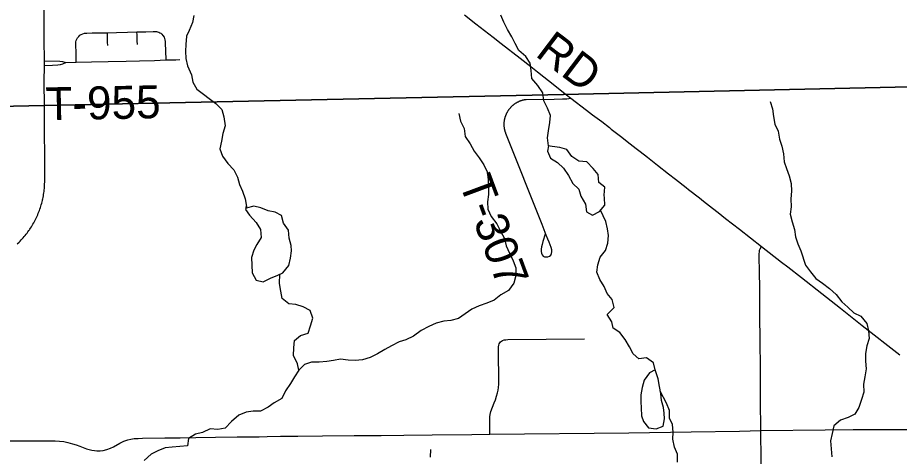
# Model space of a CAD drawing. Extents: x 0 to 34, y 0 to 22.
# Drawn here: x 5.217 to 5.977, y 17.563 to 17.941 of the extents above; entities that cross this region are included whole.
import ezdxf

# ---------------------------------------------------------------- set-up
doc = ezdxf.new("R2010")
doc.units = 0
for name, color, linetype in [('GM_X_County_Road', 7, 'Continuous'), ('GM_X_Minor_Lake', 7, 'Continuous'), ('GM_X_Minor_River', 7, 'Continuous'), ('GM_X_Township', 7, 'Continuous'), ('GM_X_Township_Road', 7, 'Continuous'), ('GM_X_Township_Road_Text', 7, 'Continuous'), ('GM_X_US_Route', 7, 'Continuous')]:
    doc.layers.add(name, color=color, linetype=linetype)

msp = doc.modelspace()

# ---------------------------------------------------------------- linework, layer by layer
at = {"layer": 'GM_X_County_Road'}
msp.add_lwpolyline([(5.20847, 17.576), (5.22729, 17.57592), (5.2446, 17.57599), (5.24938, 17.57584), (5.25317, 17.57558), (5.25684, 17.57531), (5.26026, 17.57464), (5.26428, 17.5734), (5.26745, 17.57247), (5.27072, 17.5713), (5.27635, 17.56911), (5.28089, 17.56785), (5.28316, 17.56752), (5.28535, 17.56735), (5.28803, 17.56726), (5.2908, 17.5676), (5.29383, 17.56836), (5.29702, 17.56962), (5.29962, 17.57089), (5.30509, 17.57399), (5.30854, 17.57567), (5.31215, 17.57693), (5.31465, 17.57744), (5.31761, 17.57785), (5.32105, 17.5781), (5.32475, 17.57819), (5.34394, 17.5784), (5.35406, 17.57854), (5.35715, 17.57859), (5.37072, 17.57877), (5.38758, 17.57901), (5.40628, 17.57927), (5.40937, 17.57931), (5.42518, 17.57953), (5.43204, 17.5797), (5.44364, 17.57987), (5.45345, 17.57992), (5.45857, 17.58), (5.47981, 17.58029), (5.50715, 17.58046), (5.53059, 17.58062), (5.54992, 17.58079), (5.57437, 17.58113), (5.60882, 17.58138), (5.62419, 17.58163), (5.74417, 17.58272), (5.79777, 17.58365), (5.83962, 17.5844), (5.8578, 17.58483), (5.91351, 17.58548), (5.93758, 17.5857), (5.96129, 17.58577), (5.99322, 17.58584)], dxfattribs=at)
at = {"layer": 'GM_X_Minor_Lake'}
for points in [[(5.67477, 17.83028), (5.67405, 17.82565), (5.67651, 17.81958), (5.68257, 17.81598), (5.68786, 17.81086), (5.69203, 17.8046), (5.69581, 17.79778), (5.70111, 17.79285), (5.70263, 17.78678), (5.70679, 17.77995), (5.70755, 17.77331), (5.71285, 17.77047), (5.7189, 17.7737), (5.72325, 17.77901), (5.72306, 17.78546)], [(5.67475, 17.83016), (5.67405, 17.82565), (5.67651, 17.81958), (5.68257, 17.81598), (5.68786, 17.81086), (5.69203, 17.8046), (5.69581, 17.79778), (5.70111, 17.79285), (5.70263, 17.78678), (5.70679, 17.77995), (5.70755, 17.77331), (5.71285, 17.77047), (5.7189, 17.7737), (5.72325, 17.77901), (5.72306, 17.78546)], [(5.72306, 17.78546), (5.72268, 17.78755), (5.72343, 17.79457), (5.71813, 17.79855), (5.71756, 17.80538), (5.71321, 17.81069), (5.70791, 17.81637), (5.7011, 17.81694), (5.69486, 17.82092), (5.69069, 17.82699), (5.68445, 17.82869), (5.67783, 17.82964), (5.67457, 17.83032)], [(5.72306, 17.78546), (5.72268, 17.78755), (5.72343, 17.79457), (5.71813, 17.79855), (5.71756, 17.80538), (5.71321, 17.81069), (5.70791, 17.81637), (5.7011, 17.81694), (5.69486, 17.82092), (5.69069, 17.82699), (5.68445, 17.82869), (5.67783, 17.82964), (5.67477, 17.83028)], [(5.41423, 17.77784), (5.41342, 17.77543), (5.41682, 17.7705), (5.42269, 17.76405), (5.42629, 17.75798), (5.42686, 17.75134), (5.42327, 17.74527), (5.42062, 17.74015), (5.41854, 17.73389), (5.41892, 17.72744), (5.4193, 17.72061), (5.42271, 17.71435), (5.42876, 17.71302), (5.43519, 17.71606), (5.44125, 17.71872)], [(5.41411, 17.77748), (5.41342, 17.77543), (5.41682, 17.7705), (5.42269, 17.76405), (5.42629, 17.75798), (5.42686, 17.75134), (5.42327, 17.74527), (5.42062, 17.74015), (5.41854, 17.73389), (5.41892, 17.72744), (5.4193, 17.72061), (5.42271, 17.71435), (5.42876, 17.71302), (5.43519, 17.71606), (5.44125, 17.71872)], [(5.44125, 17.71872), (5.4456, 17.72081), (5.45089, 17.72707), (5.45221, 17.73334), (5.45315, 17.73959), (5.45296, 17.74434), (5.45107, 17.7506), (5.4505, 17.75762), (5.44615, 17.76368), (5.44444, 17.77013), (5.43895, 17.77316), (5.43309, 17.7743), (5.42685, 17.77676), (5.4206, 17.77809), (5.41417, 17.77657), (5.41407, 17.77798)], [(5.44125, 17.71872), (5.4456, 17.72081), (5.45089, 17.72707), (5.45221, 17.73334), (5.45315, 17.73959), (5.45296, 17.74434), (5.45107, 17.7506), (5.4505, 17.75762), (5.44615, 17.76368), (5.44444, 17.77013), (5.43895, 17.77316), (5.43309, 17.7743), (5.42685, 17.77676), (5.4206, 17.77809), (5.41417, 17.77657), (5.41411, 17.77748)], [(5.76692, 17.63711), (5.76189, 17.63448), (5.75735, 17.62822), (5.75565, 17.62196), (5.75452, 17.61551), (5.75453, 17.60944), (5.75472, 17.60451), (5.7551, 17.59749), (5.7568, 17.59256), (5.76115, 17.58706)], [(5.76691, 17.63711), (5.76189, 17.63448), (5.75735, 17.62822), (5.75565, 17.62196), (5.75452, 17.61551), (5.75453, 17.60944), (5.75472, 17.60451), (5.7551, 17.59749), (5.7568, 17.59256), (5.76115, 17.58706)], [(5.76115, 17.58706), (5.76759, 17.5863), (5.77364, 17.58858), (5.77477, 17.59503), (5.77458, 17.59977), (5.77401, 17.60471), (5.77212, 17.61077), (5.77155, 17.61685), (5.7706, 17.62291), (5.76946, 17.62936), (5.76692, 17.63711)], [(5.76115, 17.58706), (5.76759, 17.5863), (5.77364, 17.58858), (5.77477, 17.59503), (5.77458, 17.59977), (5.77401, 17.60471), (5.77212, 17.61077), (5.77155, 17.61685), (5.7706, 17.62291), (5.76946, 17.62936), (5.76694, 17.63704)]]:
    msp.add_lwpolyline(points, dxfattribs=at)
at = {"layer": 'GM_X_Minor_River'}
for points in [[(5.36902, 17.94261), (5.36765, 17.93651), (5.36478, 17.92961), (5.36263, 17.92463), (5.36203, 17.91759)], [(5.67475, 17.83016), (5.67402, 17.83698), (5.67482, 17.84325), (5.67599, 17.8503), (5.67641, 17.85638), (5.674, 17.86259), (5.67083, 17.86897), (5.66991, 17.87596), (5.66561, 17.88212), (5.66036, 17.88826), (5.65983, 17.89508), (5.65912, 17.90133), (5.65539, 17.90731), (5.64922, 17.91229), (5.64606, 17.91829), (5.64327, 17.9243), (5.63935, 17.93047), (5.63636, 17.93685), (5.63377, 17.94286)], [(5.36203, 17.91759), (5.36179, 17.91171), (5.36212, 17.90545), (5.3634, 17.89903), (5.36679, 17.89152), (5.36807, 17.8851), (5.37143, 17.87892), (5.37739, 17.87488), (5.3822, 17.87101), (5.38779, 17.86658), (5.3932, 17.86159), (5.39486, 17.85517), (5.39598, 17.84742), (5.39386, 17.84092), (5.39288, 17.83426), (5.39133, 17.82758), (5.39356, 17.82118), (5.39824, 17.81503), (5.40348, 17.80946), (5.40646, 17.80308), (5.4083, 17.79686), (5.4109, 17.79104), (5.41313, 17.78445), (5.41423, 17.77784)], [(5.866, 17.86855), (5.86804, 17.86215), (5.86876, 17.85552), (5.87004, 17.84891), (5.87283, 17.84291), (5.87393, 17.8361), (5.87615, 17.82989), (5.87744, 17.82328), (5.87817, 17.81647), (5.88, 17.81063), (5.88223, 17.80423), (5.88408, 17.79782), (5.88424, 17.791), (5.88382, 17.78454), (5.88397, 17.77771), (5.88318, 17.77124), (5.88503, 17.76464), (5.88707, 17.75824), (5.88778, 17.75181), (5.88981, 17.74578), (5.89241, 17.73977), (5.89648, 17.72734), (5.90077, 17.72156), (5.90525, 17.71578), (5.91121, 17.71194), (5.91718, 17.70714), (5.92297, 17.70197), (5.92765, 17.69562), (5.93286, 17.69119), (5.93827, 17.68638), (5.9442, 17.6833), (5.94926, 17.67715), (5.95092, 17.67074), (5.95126, 17.66411), (5.94933, 17.6578), (5.94834, 17.65133), (5.94831, 17.6445), (5.94884, 17.63806), (5.94767, 17.6312), (5.9465, 17.62473), (5.94665, 17.6179), (5.94472, 17.61159), (5.94242, 17.60471), (5.93896, 17.59894), (5.93316, 17.59596), (5.92659, 17.59391), (5.92103, 17.58885), (5.91948, 17.58236), (5.91812, 17.57588), (5.91919, 17.56225)], [(5.59752, 17.85797), (5.59899, 17.85155), (5.60197, 17.84517), (5.60308, 17.83837), (5.60739, 17.83183), (5.61056, 17.82564), (5.61504, 17.81986), (5.61915, 17.81389), (5.62193, 17.80788), (5.62284, 17.80126), (5.62317, 17.7952), (5.62295, 17.78836), (5.62234, 17.7819), (5.62249, 17.77564), (5.62528, 17.76944), (5.63034, 17.76292), (5.63332, 17.75673), (5.63687, 17.75036), (5.63834, 17.74394), (5.64114, 17.73756), (5.64431, 17.73118), (5.64672, 17.72517), (5.64669, 17.71834), (5.64494, 17.71185), (5.64017, 17.70566), (5.63383, 17.70191), (5.62788, 17.69722), (5.62151, 17.69461), (5.61495, 17.69218), (5.60877, 17.68957), (5.603, 17.68545), (5.59724, 17.68133), (5.59065, 17.67966), (5.58462, 17.67896), (5.57803, 17.67747), (5.57149, 17.67448), (5.56495, 17.67091), (5.55844, 17.66621), (5.5517, 17.66302), (5.54607, 17.66137), (5.53953, 17.6578), (5.53355, 17.65463), (5.5274, 17.65088), (5.52104, 17.6477), (5.51447, 17.64584), (5.50805, 17.64531), (5.502, 17.64536), (5.49555, 17.64635), (5.48952, 17.64526), (5.48368, 17.64437), (5.47689, 17.64364), (5.47046, 17.64368), (5.46445, 17.64164), (5.45945, 17.63698), (5.45581, 17.63101), (5.45216, 17.62523), (5.44795, 17.61907), (5.44489, 17.61235), (5.43817, 17.60878), (5.43296, 17.60487), (5.42642, 17.60149), (5.41999, 17.60153), (5.41415, 17.60064), (5.40778, 17.59803), (5.40147, 17.59257), (5.39594, 17.58675), (5.38953, 17.58565), (5.38309, 17.58626), (5.37635, 17.58326), (5.37033, 17.58179), (5.36437, 17.57786), (5.36357, 17.57158), (5.35036, 17.57052), (5.34432, 17.57), (5.33795, 17.56738), (5.33215, 17.5644), (5.32603, 17.55914)], [(5.76694, 17.63708), (5.76548, 17.64311), (5.75932, 17.64752), (5.75272, 17.64661), (5.7479, 17.65086), (5.74454, 17.65705), (5.74099, 17.66323), (5.73632, 17.66919), (5.73056, 17.67304), (5.72949, 17.67852), (5.72537, 17.68487), (5.73147, 17.69089), (5.7298, 17.69768), (5.72533, 17.70289), (5.72292, 17.7091), (5.71919, 17.71489), (5.7164, 17.72128), (5.71739, 17.72775), (5.71931, 17.73425), (5.7241, 17.74005), (5.72603, 17.74635), (5.72645, 17.75282), (5.72575, 17.75868), (5.72428, 17.76491), (5.7197, 17.77481)], [(5.45945, 17.63698), (5.4582, 17.64226), (5.45481, 17.64958), (5.45504, 17.65623), (5.45565, 17.6625), (5.46104, 17.66661), (5.46742, 17.66865), (5.46954, 17.67515), (5.47147, 17.68165), (5.46924, 17.68843), (5.46311, 17.69151), (5.45683, 17.69345), (5.45076, 17.69407), (5.44518, 17.69849), (5.44389, 17.70491), (5.4428, 17.71153), (5.44308, 17.71948)], [(5.78616, 17.55765), (5.78601, 17.56448), (5.78341, 17.57049), (5.78212, 17.57748), (5.78235, 17.58355), (5.78183, 17.58999), (5.77924, 17.59562), (5.77909, 17.60207), (5.77648, 17.60846), (5.77114, 17.61872)], [(5.57313, 17.56183), (5.57336, 17.56847)]]:
    msp.add_lwpolyline(points, dxfattribs=at)
at = {"layer": 'GM_X_Township'}
for points in [[(6.70537, 19.6821), (6.70963, 19.16766), (6.71042, 19.04387), (6.71169, 18.92788), (6.71262, 18.76776), (6.71518, 18.37415), (6.71961, 17.89693), (6.52686, 17.89276), (6.52166, 17.89265), (6.51777, 17.89256), (6.14296, 17.88445), (5.68786, 17.8746), (5.23962, 17.86489), (4.75674, 17.85444)], [(4.29417, 16.81303), (4.29258, 17.16739), (4.29139, 17.31008), (4.28969, 17.51278), (4.28798, 17.71737), (4.28678, 17.83811), (4.28685, 17.84011), (4.28692, 17.84212), (4.28987, 17.8422), (4.75674, 17.85444), (5.23962, 17.86489), (5.68786, 17.8746), (6.14296, 17.88445), (6.51777, 17.89256), (6.52166, 17.89265), (6.52686, 17.89276), (6.71961, 17.89693), (6.72194, 17.73847), (6.72576, 17.34372), (6.73112, 16.77245)]]:
    msp.add_lwpolyline(points, dxfattribs=at)
at = {"layer": 'GM_X_Township_Road'}
msp.add_line((5.68625, 17.87747), (5.69023, 17.87429), dxfattribs=at)
for points in [[(5.60249, 17.94312), (5.61222, 17.93546), (5.627, 17.92399), (5.63397, 17.91851), (5.65037, 17.90585), (5.65961, 17.89859), (5.66544, 17.894), (5.68027, 17.88224), (5.68625, 17.87747)], [(5.26757, 17.90238), (5.26731, 17.91058), (5.26711, 17.91692), (5.26723, 17.91976), (5.26751, 17.92103), (5.26799, 17.92215), (5.26867, 17.92339), (5.26967, 17.92454), (5.2707, 17.9255), (5.2719, 17.92626), (5.27329, 17.92686), (5.27469, 17.92725), (5.27661, 17.92746), (5.28132, 17.92757), (5.29436, 17.92774), (5.3023, 17.92792), (5.3116, 17.92814), (5.3199, 17.92834), (5.3274, 17.92861), (5.33378, 17.92877), (5.33661, 17.92869), (5.33769, 17.92841), (5.33869, 17.92809), (5.33949, 17.9277), (5.3404, 17.92718), (5.34132, 17.92634), (5.34224, 17.92534), (5.34324, 17.92374), (5.34367, 17.92267), (5.34403, 17.92155), (5.34423, 17.9202), (5.34427, 17.91871), (5.34448, 17.91206), (5.34472, 17.90421)], [(5.29469, 17.91669), (5.2946, 17.91967), (5.29446, 17.92441), (5.29436, 17.92774)], [(5.32022, 17.91749), (5.32012, 17.92084), (5.31999, 17.92547), (5.3199, 17.92834)], [(5.24, 17.90343), (5.25328, 17.9033), (5.25575, 17.90288), (5.2586, 17.90205)], [(5.24001, 17.89931), (5.24699, 17.89986), (5.25152, 17.9), (5.2539, 17.9002), (5.25605, 17.90083), (5.2586, 17.90205)], [(5.2586, 17.90205), (5.26757, 17.90238), (5.28062, 17.90266), (5.29519, 17.90299), (5.31053, 17.90331), (5.32207, 17.90355), (5.33502, 17.90388), (5.34472, 17.90421), (5.34857, 17.90432), (5.35343, 17.90445), (5.35694, 17.90455)], [(5.67204, 17.75402), (5.67003, 17.74786), (5.66932, 17.74527), (5.66878, 17.74312), (5.66842, 17.7412), (5.66847, 17.73919), (5.66869, 17.73763), (5.66941, 17.73629), (5.6703, 17.73526), (5.67142, 17.73463), (5.67284, 17.73445), (5.67432, 17.73459), (5.67554, 17.73511), (5.67673, 17.73602), (5.6774, 17.73736), (5.67772, 17.73883), (5.67763, 17.74053), (5.677, 17.74259), (5.67633, 17.74477), (5.67544, 17.7471), (5.67432, 17.74987), (5.67291, 17.7532), (5.66923, 17.76238), (5.63806, 17.84087), (5.63789, 17.84134), (5.63776, 17.8417), (5.63764, 17.84205), (5.63753, 17.84242), (5.63742, 17.84278), (5.63732, 17.84314), (5.63722, 17.84351), (5.63713, 17.84388), (5.63705, 17.84425), (5.63698, 17.84462), (5.63691, 17.84499), (5.63685, 17.84537), (5.63679, 17.84574), (5.63674, 17.84612), (5.6367, 17.8465), (5.63667, 17.84687), (5.63671, 17.85104), (5.63675, 17.85141), (5.6368, 17.85179), (5.63685, 17.85217), (5.63692, 17.85254), (5.63699, 17.85291), (5.63706, 17.85328), (5.63714, 17.85365), (5.63723, 17.85402), (5.63733, 17.85439), (5.63743, 17.85475), (5.63754, 17.85512), (5.63765, 17.85548), (5.63777, 17.85584), (5.6379, 17.8562), (5.63803, 17.85655), (5.63817, 17.8569), (5.63832, 17.85725), (5.63847, 17.8576), (5.63863, 17.85794), (5.63879, 17.85829), (5.63896, 17.85863), (5.63914, 17.85896), (5.63932, 17.8593), (5.6395, 17.85963), (5.6397, 17.85995), (5.63989, 17.86027), (5.6401, 17.86059), (5.64031, 17.86091), (5.64052, 17.86122), (5.64074, 17.86153), (5.64097, 17.86184), (5.6412, 17.86214), (5.64144, 17.86243), (5.64168, 17.86273), (5.64193, 17.86301), (5.64218, 17.8633), (5.64243, 17.86358), (5.64269, 17.86385), (5.64296, 17.86412), (5.64323, 17.86439), (5.64351, 17.86465), (5.64379, 17.8649), (5.64407, 17.86516), (5.64436, 17.8654), (5.64465, 17.86564), (5.64495, 17.86588), (5.64525, 17.86611), (5.64555, 17.86633), (5.64586, 17.86655), (5.64618, 17.86677), (5.64649, 17.86698), (5.64681, 17.86718), (5.64714, 17.86738), (5.64746, 17.86757), (5.64779, 17.86776), (5.64813, 17.86794), (5.64846, 17.86811), (5.6488, 17.86828), (5.64914, 17.86844), (5.64949, 17.8686), (5.64984, 17.86875), (5.65019, 17.8689), (5.65054, 17.86903), (5.65089, 17.86917), (5.65125, 17.86929), (5.65161, 17.86941), (5.65197, 17.86953), (5.65234, 17.86963), (5.6527, 17.86973), (5.65307, 17.86983), (5.65344, 17.86992), (5.65381, 17.87), (5.65418, 17.87007), (5.65455, 17.87014), (5.65493, 17.8702), (5.6553, 17.87026), (5.65566, 17.87018), (5.67982, 17.87038), (5.68684, 17.8706), (5.69074, 17.87082), (5.6941, 17.87132)], [(5.69023, 17.87429), (5.6941, 17.87132), (5.70745, 17.86099), (5.71273, 17.85693), (5.72079, 17.85108), (5.72738, 17.84593), (5.72767, 17.8457), (5.72892, 17.84472), (5.73693, 17.83846), (5.74513, 17.83206), (5.74629, 17.83115), (5.74666, 17.83086), (5.75757, 17.82234), (5.76013, 17.82034), (5.76881, 17.81356), (5.77836, 17.8061), (5.78433, 17.80144), (5.79356, 17.79423), (5.79561, 17.79263), (5.80492, 17.78536), (5.80845, 17.7826), (5.81626, 17.7765), (5.82108, 17.77273), (5.82752, 17.7677), (5.8335, 17.76303), (5.83948, 17.75835), (5.85853, 17.74358), (5.87586, 17.73005), (5.88124, 17.72589), (5.89301, 17.71678), (5.90114, 17.71051), (5.90258, 17.70937), (5.92656, 17.69031), (5.94543, 17.67535), (5.97789, 17.65)], [(5.85846, 17.53326), (5.8578, 17.58483), (5.85766, 17.6113), (5.85759, 17.63552), (5.85722, 17.6654), (5.85715, 17.68111), (5.85708, 17.69304), (5.85693, 17.70948), (5.85679, 17.71966), (5.85658, 17.73682), (5.85671, 17.73908), (5.85686, 17.74017), (5.8573, 17.7414), (5.85853, 17.74358)], [(5.62419, 17.58163), (5.62431, 17.59652), (5.62456, 17.59878), (5.62515, 17.60122), (5.62649, 17.60492), (5.62783, 17.60861), (5.62901, 17.61138), (5.63002, 17.61433), (5.63086, 17.61727), (5.63136, 17.61953), (5.6317, 17.62206), (5.63187, 17.62491), (5.63163, 17.65541), (5.6317, 17.65709), (5.63193, 17.6585), (5.6322, 17.65953), (5.63271, 17.66037), (5.63355, 17.66121), (5.63422, 17.6618), (5.63506, 17.6623), (5.63657, 17.66289), (5.638, 17.66314), (5.63985, 17.66323), (5.70572, 17.6639)]]:
    msp.add_lwpolyline(points, dxfattribs=at)
at = {"layer": 'GM_X_US_Route'}
for points in [[(5.24014, 17.86435), (5.23996, 17.88547), (5.24001, 17.89931), (5.24, 17.90343), (5.23996, 17.92179), (5.23992, 17.94227), (5.23998, 17.95984), (5.24002, 17.97041), (5.24011, 17.99394), (5.24014, 18.00177), (5.24022, 18.0225), (5.24038, 18.06668), (5.24044, 18.08249), (5.24054, 18.10767), (5.24062, 18.12803), (5.24053, 18.1584), (5.24088, 18.19015), (5.24097, 18.2117), (5.24105, 18.23079), (5.24114, 18.25217), (5.24119, 18.2645), (5.24123, 18.27319), (5.24163, 18.38972)], [(5.21666, 17.74567), (5.2182, 17.74722), (5.21912, 17.74815), (5.22002, 17.7491), (5.2209, 17.75005), (5.22177, 17.75103), (5.22263, 17.75202), (5.22346, 17.75302), (5.22428, 17.75404), (5.22508, 17.75508), (5.22586, 17.75612), (5.22662, 17.75718), (5.22712, 17.75791), (5.22737, 17.75826), (5.22809, 17.75935), (5.2288, 17.76045), (5.22948, 17.76155), (5.23015, 17.76268), (5.2308, 17.76381), (5.23143, 17.76496), (5.23204, 17.76612), (5.23262, 17.76728), (5.23319, 17.76846), (5.23374, 17.76964), (5.23426, 17.77084), (5.23477, 17.77205), (5.23525, 17.77326), (5.23531, 17.77341), (5.23571, 17.77448), (5.23616, 17.77571), (5.23657, 17.77695), (5.23697, 17.77819), (5.23735, 17.77944), (5.2377, 17.7807), (5.23803, 17.78197), (5.23834, 17.78323), (5.23845, 17.78372), (5.23863, 17.78451), (5.2389, 17.78579), (5.23914, 17.78707), (5.23936, 17.78836), (5.23956, 17.78965), (5.23973, 17.79095), (5.23989, 17.79224), (5.24002, 17.79354), (5.24005, 17.79394), (5.24013, 17.79484), (5.24021, 17.79615), (5.24027, 17.79745), (5.24031, 17.79876), (5.24014, 17.86435)]]:
    msp.add_lwpolyline(points, dxfattribs=at)

# ---------------------------------------------------------------- texts
at = {"layer": 'GM_X_Township_Road_Text'}
for s, rotation, p in [('RD', 322.85019, (5.66248, 17.90825)), ('T-955', 1.12376, (5.24125, 17.85216)), ('T-307', 290.39109, (5.5974, 17.79886))]:
    msp.add_text(s, height=0.028409, rotation=rotation, dxfattribs=at).set_placement(p)

doc.saveas('drawing.dxf')
